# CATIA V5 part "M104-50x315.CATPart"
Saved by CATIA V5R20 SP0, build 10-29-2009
Part number: M104-50x315
Source: Unknown
Bounding box of the stored display mesh (mm): x -24.865 to 24.865, y -24.997 to 24.997, z 0 to 315
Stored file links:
  C:\Users\Utente\Desktop\IO LAVORO\3D X SITO CF\X SITO\M104\M104-50x315.CATPart
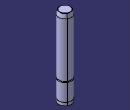
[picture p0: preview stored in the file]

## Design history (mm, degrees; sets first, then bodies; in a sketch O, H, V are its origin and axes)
Body1 (main body)
  Solid1 "PartBody": solid without history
